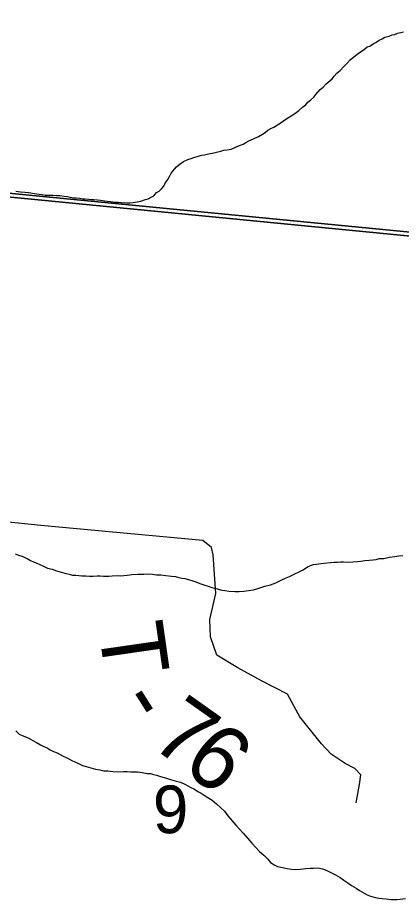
# Model space of a CAD drawing. Extents: x 1310247 to 1664935, y 284496 to 704931.
# Drawn here: x 1476210 to 1477989, y 513631 to 517748 of the extents above; entities that cross this region are included whole.
import ezdxf

# ---------------------------------------------------------------- set-up
doc = ezdxf.new("R2010")
doc.units = 0
for name, color, linetype in [('GM_X_Adjacent_County', 7, 'Continuous'), ('GM_X_County', 7, 'Continuous'), ('GM_X_County_Subdivision_Text', 7, 'Continuous'), ('GM_X_Minor_River_Text', 7, 'Continuous'), ('GM_X_Township_Subdivision', 7, 'Continuous'), ('GM_X_US_Location', 7, 'Continuous')]:
    doc.layers.add(name, color=color, linetype=linetype)

msp = doc.modelspace()

# ---------------------------------------------------------------- linework, layer by layer
at = {"layer": 'GM_X_Adjacent_County'}
for points in [[(1494389.6, 515139.4), (1494077.2, 515169.8), (1493613.7, 515220.9), (1493548.6, 515228), (1490461, 515522.6), (1486739.8, 515885.3), (1486610.6, 515897.9), (1485981, 515959.2), (1485695.1, 515987.1), (1485662.1, 515990.3), (1485526, 516003.6), (1483423.4, 516208.6), (1476112, 516922.1), (1474893.7, 517040.9), (1474854.5, 517044.7), (1469475.8, 517569.3)], [(1469475.8, 517569.3), (1474854.5, 517044.7), (1474893.7, 517040.9), (1476112, 516922.1), (1483423.4, 516208.6), (1485526, 516003.6), (1485662.1, 515990.3), (1485695.1, 515987.1), (1485981, 515959.2), (1486610.6, 515897.9), (1486739.8, 515885.3), (1490461, 515522.6), (1493548.6, 515228), (1493613.7, 515220.9), (1494077.2, 515169.8), (1494389.6, 515139.4)]]:
    msp.add_lwpolyline(points, dxfattribs=at)
at = {"layer": 'GM_X_County'}
for points in [[(1475469.1, 522687.9), (1480822.4, 522169.9), (1480181.2, 516544.8), (1474875.9, 517060)], [(1474875.9, 517060), (1480181.2, 516544.8), (1479685.9, 511654.9), (1479639.7, 511215.9), (1474338.3, 511711.9)]]:
    msp.add_lwpolyline(points, close=True, dxfattribs=at)
at = {"layer": 'GM_X_County_Subdivision_Text'}
msp.add_lwpolyline([(1477779.8, 514106.3), (1477794.8, 514190.2), (1477800.9, 514235.1), (1477773.1, 514265.3), (1477729.3, 514288.1), (1477663.7, 514331), (1477619.1, 514379.8), (1477518.9, 514504), (1477461.7, 514609.6), (1477341, 514671.5), (1477231.5, 514731.6), (1477134.1, 514791.4), (1477103.4, 514876.3), (1477100.8, 514956.6), (1477129, 515076.5), (1477116.6, 515256), (1477108.2, 515290.5), (1477068.6, 515322.4), (1476316.2, 515392.3), (1475727.3, 515452.4)], dxfattribs=at)
at = {"layer": 'GM_X_Minor_River_Text'}
for points in [[(1477583.8, 517379.7), (1477592.2, 517391.4), (1477613.1, 517414.8), (1477627.5, 517426.4), (1477640.1, 517442.1), (1477669, 517465.2), (1477677.4, 517477), (1477689.9, 517490.6), (1477706.4, 517504.1), (1477723.1, 517521.6), (1477737.7, 517537.2), (1477752.3, 517552.8), (1477768.8, 517566.3), (1477789.4, 517581.7), (1477818.2, 517602.9), (1477830.6, 517612.5), (1477842.8, 517616.1), (1477859.2, 517627.6), (1477871.5, 517633.3), (1477885.9, 517644.8), (1477900.2, 517650.4), (1477912.5, 517658), (1477932.7, 517663.4), (1477947, 517669), (1477959.1, 517670.6), (1477971.3, 517676.3), (1477987.5, 517679.8), (1477999.7, 517683.4)], [(1476201, 516943.5), (1476223.1, 516940.8), (1476243.1, 516938.2), (1476259.1, 516937.7), (1476271.1, 516935.3), (1476287.1, 516932.8), (1476309.1, 516930.2), (1476323.1, 516927.7), (1476337.1, 516925.3), (1476351.1, 516924.9), (1476373.2, 516924.2), (1476389.3, 516923.7), (1476405.3, 516923.2), (1476425.3, 516920.6), (1476441.3, 516918.1), (1476453.3, 516915.7), (1476469.3, 516913.2), (1476481.3, 516912.8), (1476497.3, 516910.3), (1476511.3, 516907.9), (1476523.3, 516907.5), (1476539.4, 516907), (1476551.4, 516904.6), (1476563.4, 516904.3), (1476579.5, 516903.8), (1476593.5, 516901.3), (1476611.5, 516898.8), (1476625.4, 516896.4), (1476639.5, 516895.9), (1476651.5, 516893.5), (1476663.5, 516893.2), (1476677.6, 516892.7), (1476689.6, 516890.4), (1476713.6, 516889.6), (1476729.7, 516889.1), (1476745.8, 516890.6), (1476764, 516894.1), (1476780.2, 516897.6), (1476802.6, 516904.9), (1476814.7, 516908.5), (1476829, 516916.1), (1476841.3, 516921.8), (1476853.9, 516937.4), (1476866.1, 516943), (1476876.5, 516954.7), (1476887, 516966.4), (1476895.6, 516984.2), (1476906.1, 516997.9), (1476914.6, 517011.6), (1476921.1, 517027.5), (1476937.8, 517045), (1476946.2, 517056.8), (1476962.7, 517070.3), (1476979.2, 517081.8), (1476999.6, 517091.2), (1477013.8, 517094.7), (1477026, 517100.4), (1477046.3, 517105.8), (1477064.5, 517111.2), (1477076.7, 517112.8), (1477094.9, 517116.3), (1477119.1, 517121.5), (1477131.3, 517125.2), (1477151.5, 517128.6), (1477165.8, 517134.1), (1477181.9, 517135.6), (1477200.1, 517139.1), (1477216.4, 517146.6), (1477238.8, 517155.9), (1477255.1, 517161.4), (1477267.4, 517169), (1477281.7, 517176.6), (1477304.1, 517186), (1477326.6, 517197.3), (1477345.1, 517208.7), (1477357.4, 517216.4), (1477369.7, 517226), (1477384.1, 517233.6), (1477398.4, 517241.1), (1477427.1, 517258.3), (1477443.5, 517269.8), (1477458, 517281.4), (1477478.4, 517292.8), (1477494.9, 517304.3), (1477513.4, 517317.8), (1477532.1, 517335.2), (1477544.4, 517342.8), (1477554.9, 517356.5), (1477567.3, 517366.2), (1477583.8, 517379.7)], [(1476197.7, 515260.6), (1476213.5, 515254.1), (1476229.4, 515249.7), (1476253.2, 515238.9), (1476269, 515230.4), (1476282.9, 515224), (1476298.7, 515217.5), (1476312.6, 515211), (1476326.4, 515204.6), (1476348.2, 515193.9), (1476370.1, 515189.2), (1476390, 515182.6), (1476411.9, 515175.9), (1476433.8, 515169.2), (1476447.7, 515166.8), (1476463.7, 515162.3), (1476479.7, 515161.8), (1476507.8, 515158.9), (1476525.8, 515158.4), (1476541.9, 515157.9), (1476559.9, 515157.3), (1476578.1, 515158.8), (1476592.1, 515158.3), (1476608.2, 515157.8), (1476632.3, 515157.1), (1476648.4, 515158.6), (1476672.5, 515159.8), (1476688.6, 515159.3), (1476702.7, 515160.9), (1476716.8, 515162.5), (1476739.1, 515165.8), (1476767.2, 515166.9), (1476781.3, 515166.5), (1476795.3, 515166.1), (1476815.5, 515167.5), (1476835.5, 515166.8), (1476853.5, 515164.3), (1476873.6, 515163.7), (1476897.6, 515160.9), (1476923.7, 515158.1), (1476941.7, 515155.5), (1476957.6, 515151), (1476971.6, 515148.6), (1476985.5, 515146.2), (1477001.5, 515141.7), (1477021.4, 515135), (1477035.3, 515130.6), (1477055.1, 515124), (1477073, 515117.4), (1477092.9, 515110.8), (1477110.8, 515104.2), (1477128.7, 515099.7), (1477156.6, 515092.8), (1477170.6, 515090.4), (1477190.6, 515087.8), (1477216.7, 515086.9), (1477236.7, 515086.3), (1477258.9, 515087.6), (1477281.1, 515091), (1477303.3, 515094.3), (1477327.7, 515101.5), (1477356.1, 515110.7), (1477382.5, 515117.9), (1477406.9, 515127.2)], [(1477406.9, 515127.2), (1477431.4, 515138.4), (1477455.8, 515149.7), (1477470.1, 515155.3), (1477494.6, 515168.5), (1477515.1, 515177.9), (1477533.4, 515187.4), (1477554, 515200.8), (1477568.2, 515206.3), (1477582.5, 515211.9), (1477596.6, 515213.5), (1477616.8, 515216.8), (1477630.9, 515218.4), (1477661.2, 515221.5), (1477677.3, 515223), (1477693.3, 515222.5), (1477707.5, 515224.1), (1477721.5, 515223.6), (1477743.6, 515223), (1477763.7, 515224.3), (1477785.9, 515225.6), (1477802, 515227.2), (1477820.2, 515230.6), (1477840.3, 515232), (1477856.5, 515233.5), (1477872.6, 515235), (1477886.8, 515238.6), (1477908.9, 515239.9), (1477933.2, 515245.1), (1477959.4, 515248.3), (1477977.6, 515251.8), (1477995.8, 515253.2)], [(1476200.7, 514439.1), (1476216.3, 514424.6), (1476230.1, 514418.2), (1476257.9, 514407.3), (1476279.6, 514394.6), (1476297.4, 514386), (1476315.1, 514375.5), (1476330.9, 514367), (1476346.7, 514360.5), (1476360.5, 514352), (1476376.3, 514343.5), (1476392.2, 514337), (1476406, 514330.6), (1476419.8, 514322.2), (1476433.7, 514315.7), (1476447.5, 514309.3), (1476461.4, 514302.8), (1476475.2, 514296.4), (1476491, 514287.9), (1476510.8, 514279.3), (1476526.8, 514274.8), (1476548.6, 514268.1), (1476570.5, 514261.4), (1476590.5, 514258.8), (1476608.5, 514254.2), (1476628.5, 514253.6), (1476652.6, 514250.9), (1476674.6, 514250.2), (1476700.8, 514251.4), (1476716.9, 514250.9), (1476734.9, 514250.3), (1476751, 514249.8), (1476765, 514249.4), (1476787, 514246.7), (1476811, 514242), (1476825.1, 514241.5), (1476839, 514237.1), (1476853, 514234.6), (1476872.8, 514228), (1476888.8, 514223.5), (1476904.7, 514219), (1476918.6, 514214.6), (1476940.5, 514207.9), (1476964.4, 514201.2), (1476988.1, 514190.4)], [(1476988.1, 514190.4), (1477009.8, 514177.7), (1477029.6, 514169.1), (1477045.3, 514158.6), (1477061.1, 514150.1), (1477074.9, 514141.7), (1477096.5, 514127), (1477112.3, 514118.5), (1477131.9, 514101.8), (1477151.4, 514083.2), (1477168.9, 514066.6), (1477184.3, 514046.1), (1477203.6, 514023.5), (1477221, 514002.9), (1477238.5, 513984.3), (1477256, 513965.8), (1477275.3, 513941.1), (1477296.6, 513918.4), (1477314, 513897.8), (1477331.5, 513879.3), (1477351, 513862.6), (1477370.5, 513844), (1477382.1, 513829.6), (1477401.8, 513817), (1477415.6, 513810.6), (1477437.6, 513805.9), (1477459.5, 513801.2), (1477479.5, 513798.6), (1477497.5, 513796), (1477521.7, 513797.3), (1477545.9, 513800.5), (1477566, 513801.9), (1477582.1, 513803.4), (1477602.3, 513804.8), (1477624.2, 513800.1), (1477644, 513791.5), (1477661.8, 513782.9), (1477683.6, 513772.2), (1477705.3, 513759.6), (1477723, 513747), (1477740.6, 513734.4), (1477758.3, 513721.8), (1477780, 513709.2), (1477795.7, 513698.7), (1477817.4, 513686), (1477831.2, 513679.5), (1477847.1, 513673), (1477869, 513666.3), (1477885, 513663.8), (1477901, 513661.3), (1477919, 513660.8), (1477943, 513658), (1477969.1, 513657.2), (1477983.3, 513658.8), (1478009.5, 513662)]]:
    msp.add_lwpolyline(points, dxfattribs=at)

# ---------------------------------------------------------------- texts
at = {"layer": 'GM_X_Township_Subdivision'}
for s, rotation, p in [('T', 278.1834, (1476583.1, 514921.3)), ('-', 302.3647, (1476662.6, 514570.6)), ('7', 324.7124, (1476815.8, 514374.7)), ('6', 321.2419, (1476962.8, 514270.8))]:
    msp.add_text(s, height=300, rotation=rotation, dxfattribs=at).set_placement(p)
at = {"layer": 'GM_X_US_Location'}
msp.add_text('9', height=221, rotation=0, dxfattribs=at).set_placement((1476836.8, 513964.9))

doc.saveas('drawing.dxf')
